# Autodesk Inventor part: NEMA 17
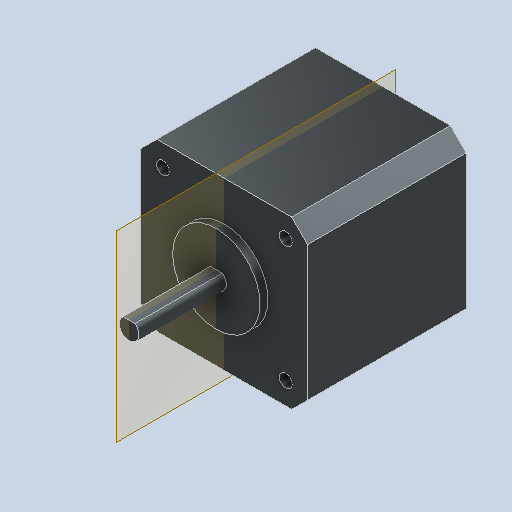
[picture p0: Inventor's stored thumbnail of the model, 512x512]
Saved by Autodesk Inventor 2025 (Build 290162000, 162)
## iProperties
Created: 2026-03
Part Number: NEMA 17
Material: Generico
Description: NEMA 17
Document SubType Name: Modeling
Designer: R5800u
Density: 1 g/cm^3
Appearance: Grigio ferro
Author: R5800u
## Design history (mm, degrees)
node "NEMA 17"
sketch "Schizzo1"
  geometry: L1 (-2.707, 42)-(39.293, 42); L2 (39.293, 42)-(39.293, 0); L3 (39.293, 0)-(-2.707, 0); L4 (-2.707, 0)-(-2.707, 42); L5 (-2.707, 42)-(39.293, 0); L6 (39.293, 42)-(-2.707, 0); L7 (50.204, 58.756)-(-13.618, 58.756); L8 (-13.618, 58.756)-(-13.618, -16.756); L9 (-13.618, -16.756)-(50.204, -16.756); L10 (50.204, -16.756)-(50.204, 58.756); L11 (50.204, 58.756)-(-13.618, -16.756); L12 (-13.618, 58.756)-(50.204, -16.756); A1 r 2.5 centre (18.293, 21) between (16.793, 23) and (19.793, 23) reference; 1 further point
  constraints: 24 end point, 4 midpoint, 4 parallel, 2 horizontal, 2 perpendicular
  dimensions: "d0" = 42 distance of L2.end L3.end; "d1" = 42 distance of L1.end L2.end
extrude "Estrusione1" cut sketch "Schizzo1" extent not by distance; stored distance "d2" = 0; taper "d3" = 0 deg
sketch "Schizzo2"
  geometry: L1 (1.5, 2)-(-1.5, 2) reference; A1 r 2.5 centre (0, 0) between (-1.5, 2) and (1.5, 2) reference; 1 further point
extrude "Estrusione2" cut sketch "Schizzo2" distance "d4" = 1; taper "d5" = 0 deg
chamfer "Smusso1" distance "d6" = 4; stored, may be unused: second distance "d7" = 2, angle "d8" = 45 deg
sketch "Schizzo3"
  geometry: L1 (38, -38)-(34, -42) reference; L2 (38, -38)-(38, -4) reference; L3 (34, 0)-(38, -4) reference; L4 (34, 0)-(0, 0) reference; L5 (-4, -4)-(0, 0) reference; L6 (-4, -4)-(-4, -38) reference; L7 (0, -42)-(-4, -38) reference; L8 (0, -42)-(34, -42) reference; C1 r 1.6 at (1.5, -5.5) reference; C2 r 1.6 at (1.5, -36.5) reference; C3 r 1.6 at (32.5, -36.5) reference; C4 r 1.6 at (32.5, -5.5) reference; 1 further point
extrude "Estrusione3" join sketch "Schizzo3" distance "d9" = 2; taper "d10" = 0 deg
node "Solido1"
node "Linea chiusa proiettata1"
node "Linea chiusa proiettata2"
